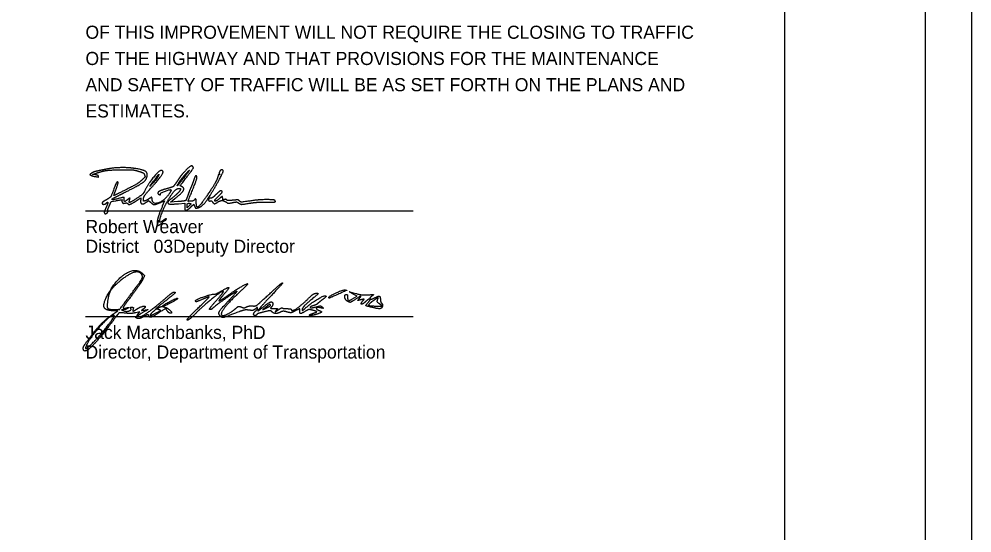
# Model space of a CAD drawing. Extents: x 0 to 34, y 0 to 22.
# Drawn here: x 23.82 to 34, y 5.49 to 10.97 of the extents above; entities that cross this region are included whole.
import ezdxf

# ---------------------------------------------------------------- set-up
doc = ezdxf.new("R2010")
doc.units = 0
for name, color, linetype in [('SH_Border', 7, 'Continuous'), ('SH_Cut_Line', 7, 'Continuous'), ('SH_Data', 7, 'Continuous'), ('SH_Text', 7, 'Continuous')]:
    doc.layers.add(name, color=color, linetype=linetype)

msp = doc.modelspace()

# ---------------------------------------------------------------- linework, layer by layer
at = {"layer": 'SH_Border'}
msp.add_line((32, 0.5), (32, 21.5), dxfattribs=at)
msp.add_lwpolyline([(1.5, 21.5), (33.5, 21.5), (33.5, 0.5), (1.5, 0.5)], close=True, dxfattribs=at)
at = {"layer": 'SH_Cut_Line'}
msp.add_lwpolyline([(0, 0), (34, 0), (34, 22), (0, 22)], close=True, dxfattribs=at)
at = {"layer": 'SH_Data'}
for p, q in [((24.528, 8.926), (28.028, 8.926)), ((24.528, 7.797), (28.028, 7.797))]:
    msp.add_line(p, q, dxfattribs=at)
at = {"layer": 'SH_Text'}
for p, q in [((24.99, 8.002), (24.99, 8.002)), ((27.129, 8.001), (27.129, 8.001)), ((25.311, 7.87), (25.311, 7.87)), ((25.356, 7.912), (25.356, 7.912)), ((25.727, 7.883), (25.727, 7.883)), ((26.504, 7.914), (26.504, 7.914)), ((27.582, 7.895), (27.582, 7.895))]:
    msp.add_line(p, q, dxfattribs=at)
for points in [[(24.633, 9.309), (24.603, 9.313), (24.63, 9.322)], [(25.249, 9.219), (25.216, 9.183), (25.256, 9.242)], [(24.782, 8.975), (24.803, 9.023), (24.852, 9.032)], [(25.182, 9.02), (25.202, 9.036), (25.223, 9.016)], [(25.331, 9.014), (25.374, 9.032), (25.349, 8.973)], [(25.514, 9.023), (25.435, 9.018), (25.484, 9.056)], [(25.521, 9), (25.59, 9.005), (25.59, 8.966)], [(25.636, 8.978), (25.613, 8.955), (25.613, 8.976)], [(25.662, 8.973), (25.684, 8.996), (25.694, 8.973)], [(27.393, 7.991), (27.43, 8.013), (27.389, 8.036)], [(24.843, 7.835), (24.873, 7.856), (24.835, 7.857)], [(25.085, 7.815), (25.107, 7.847), (25.065, 7.837)], [(26.453, 7.894), (26.423, 7.869), (26.464, 7.888)], [(27.642, 7.908), (27.698, 7.908), (27.669, 7.93)]]:
    msp.add_lwpolyline(points, dxfattribs=at)
for points in [[(25.045, 9.378), (24.973, 9.388), (24.809, 9.382), (24.736, 9.366)], [(25.183, 9.279), (25.197, 9.326), (25.145, 9.364), (25.045, 9.378)], [(25.665, 9.404), (25.656, 9.41), (25.569, 9.328), (25.541, 9.289)], [(25.591, 9.259), (25.672, 9.364), (25.686, 9.391), (25.665, 9.404)], [(24.59, 9.324), (24.574, 9.311), (24.574, 9.311), (24.588, 9.303)], [(24.588, 9.303), (24.596, 9.299), (24.618, 9.293), (24.636, 9.29)], [(24.647, 9.347), (24.625, 9.342), (24.6, 9.332), (24.59, 9.324)], [(24.63, 9.322), (24.708, 9.349), (24.802, 9.362), (24.927, 9.362)], [(24.666, 9.295), (24.664, 9.3), (24.649, 9.307), (24.633, 9.309)], [(24.636, 9.29), (24.663, 9.285), (24.669, 9.286), (24.666, 9.295)], [(24.736, 9.366), (24.709, 9.36), (24.669, 9.352), (24.647, 9.347)], [(24.927, 9.362), (25.036, 9.361), (25.059, 9.359), (25.102, 9.345)], [(24.965, 9.13), (25.097, 9.196), (25.173, 9.248), (25.183, 9.279)], [(25.102, 9.345), (25.142, 9.331), (25.153, 9.324), (25.159, 9.307)], [(25.159, 9.307), (25.165, 9.289), (25.163, 9.283), (25.143, 9.265)], [(25.336, 9.354), (25.312, 9.354), (25.202, 9.217), (25.161, 9.137)], [(25.228, 9.167), (25.322, 9.27), (25.371, 9.355), (25.336, 9.354)], [(25.295, 9.278), (25.287, 9.265), (25.267, 9.238), (25.249, 9.219)], [(25.256, 9.242), (25.295, 9.299), (25.322, 9.324), (25.295, 9.278)], [(25.541, 9.289), (25.532, 9.276), (25.512, 9.246), (25.495, 9.222)], [(25.572, 9.268), (25.526, 9.207), (25.499, 9.182), (25.526, 9.224)], [(25.526, 9.224), (25.544, 9.253), (25.584, 9.302), (25.615, 9.335)], [(25.615, 9.335), (25.644, 9.365), (25.628, 9.341), (25.572, 9.268)], [(25.675, 9.155), (25.712, 9.248), (25.723, 9.295), (25.708, 9.3)], [(25.708, 9.3), (25.704, 9.301), (25.694, 9.28), (25.685, 9.254)], [(25.944, 9.296), (25.936, 9.261), (25.895, 9.188), (25.836, 9.102)], [(25.928, 9.204), (25.988, 9.31), (26.006, 9.362), (25.983, 9.362)], [(25.957, 9.312), (25.952, 9.315), (25.946, 9.309), (25.944, 9.296)], [(25.983, 9.362), (25.971, 9.362), (25.953, 9.326), (25.96, 9.315)], [(25.96, 9.315), (25.963, 9.31), (25.962, 9.309), (25.957, 9.312)], [(24.836, 9.171), (24.803, 9.081), (24.793, 9.067), (24.748, 9.041)], [(24.866, 9.231), (24.861, 9.229), (24.847, 9.202), (24.836, 9.171)], [(24.849, 9.139), (24.873, 9.204), (24.879, 9.236), (24.866, 9.231)], [(25.143, 9.265), (25.105, 9.228), (25.056, 9.198), (24.944, 9.142)], [(25.148, 9.044), (25.148, 9.07), (25.169, 9.103), (25.228, 9.167)], [(25.434, 9.171), (25.371, 9.155), (25.306, 9.13), (25.302, 9.12)], [(25.413, 9.043), (25.446, 9.101), (25.506, 9.164), (25.526, 9.164)], [(25.495, 9.222), (25.471, 9.187), (25.46, 9.178), (25.434, 9.171)], [(25.484, 9.056), (25.559, 9.113), (25.589, 9.171), (25.552, 9.185)], [(25.526, 9.164), (25.536, 9.164), (25.544, 9.16), (25.544, 9.156)], [(25.552, 9.185), (25.539, 9.19), (25.543, 9.198), (25.591, 9.259)], [(25.655, 9.175), (25.648, 9.159), (25.633, 9.121), (25.623, 9.092)], [(25.685, 9.254), (25.676, 9.227), (25.662, 9.192), (25.655, 9.175)], [(25.725, 8.955), (25.768, 8.965), (25.848, 9.063), (25.928, 9.204)], [(24.813, 9.048), (24.813, 9.051), (24.827, 9.061), (24.845, 9.07)], [(24.833, 9.088), (24.831, 9.088), (24.838, 9.111), (24.849, 9.139)], [(24.944, 9.142), (24.885, 9.112), (24.835, 9.088), (24.833, 9.088)], [(24.845, 9.07), (24.863, 9.079), (24.917, 9.106), (24.965, 9.13)], [(24.942, 9.046), (24.942, 9.068), (24.935, 9.069), (24.87, 9.053)], [(25.161, 9.137), (25.147, 9.11), (25.123, 9.088), (25.062, 9.049)], [(25.241, 9.044), (25.238, 9.069), (25.231, 9.07), (25.203, 9.05)], [(25.424, 9.109), (25.371, 9.032), (25.247, 8.988), (25.241, 9.044)], [(25.302, 9.12), (25.3, 9.114), (25.303, 9.106), (25.309, 9.102)], [(25.309, 9.102), (25.324, 9.093), (25.331, 9.094), (25.331, 9.106)], [(25.331, 9.106), (25.331, 9.117), (25.433, 9.155), (25.442, 9.147)], [(25.442, 9.147), (25.444, 9.144), (25.436, 9.127), (25.424, 9.109)], [(25.544, 9.156), (25.544, 9.144), (25.494, 9.092), (25.449, 9.057)], [(25.623, 9.092), (25.612, 9.062), (25.601, 9.036), (25.598, 9.033)], [(25.653, 9.027), (25.622, 9.027), (25.621, 9.019), (25.675, 9.155)], [(25.836, 9.102), (25.754, 8.982), (25.712, 8.952), (25.712, 9.011)], [(25.921, 9.097), (25.895, 9.072), (25.874, 9.057), (25.868, 9.06)], [(25.91, 9.035), (25.91, 9.04), (25.927, 9.06), (25.949, 9.08)], [(25.972, 9.137), (25.967, 9.137), (25.944, 9.119), (25.921, 9.097)], [(25.949, 9.08), (25.984, 9.114), (25.994, 9.137), (25.972, 9.137)], [(25.994, 9.056), (25.994, 9.077), (25.983, 9.077), (25.959, 9.055)], [(24.748, 9.041), (24.725, 9.028), (24.706, 9.013), (24.706, 9.007)], [(24.706, 9.007), (24.706, 8.994), (24.737, 8.993), (24.75, 9.005)], [(24.749, 8.962), (24.738, 8.938), (24.729, 8.914), (24.729, 8.908)], [(24.75, 9.005), (24.768, 9.024), (24.768, 9.004), (24.749, 8.962)], [(24.768, 8.928), (24.764, 8.928), (24.77, 8.949), (24.782, 8.975)], [(24.87, 9.053), (24.817, 9.04), (24.813, 9.04), (24.813, 9.048)], [(24.852, 9.032), (24.908, 9.043), (24.924, 9.044), (24.917, 9.037)], [(24.917, 9.037), (24.914, 9.035), (24.916, 9.026), (24.92, 9.017)], [(24.92, 9.017), (24.926, 9.006), (24.933, 9.003), (24.95, 9.007)], [(24.975, 9.042), (24.949, 9.022), (24.942, 9.023), (24.942, 9.046)], [(24.95, 9.007), (24.962, 9.009), (24.974, 9.008), (24.977, 9.004)], [(24.999, 9.038), (25.004, 9.061), (25, 9.062), (24.975, 9.042)], [(24.977, 9.004), (24.986, 8.989), (25.017, 8.997), (25.061, 9.025)], [(25.062, 9.049), (25.007, 9.014), (24.992, 9.011), (24.999, 9.038)], [(25.061, 9.025), (25.086, 9.041), (25.11, 9.057), (25.114, 9.059)], [(25.114, 9.059), (25.12, 9.063), (25.122, 9.058), (25.119, 9.046)], [(25.119, 9.046), (25.112, 9.006), (25.146, 8.992), (25.182, 9.02)], [(25.165, 9.031), (25.151, 9.027), (25.148, 9.029), (25.148, 9.044)], [(25.203, 9.05), (25.191, 9.042), (25.174, 9.033), (25.165, 9.031)], [(25.223, 9.016), (25.249, 8.991), (25.275, 8.991), (25.331, 9.014)], [(25.349, 8.973), (25.317, 8.897), (25.293, 8.818), (25.293, 8.79)], [(25.325, 8.802), (25.313, 8.813), (25.371, 8.973), (25.413, 9.043)], [(25.449, 9.057), (25.426, 9.039), (25.407, 9.02), (25.407, 9.015)], [(25.407, 9.015), (25.407, 9), (25.447, 8.994), (25.521, 9)], [(25.598, 9.033), (25.596, 9.031), (25.558, 9.026), (25.514, 9.023)], [(25.59, 8.966), (25.59, 8.945), (25.592, 8.928), (25.594, 8.928)], [(25.594, 8.928), (25.605, 8.928), (25.642, 8.952), (25.662, 8.973)], [(25.613, 8.976), (25.613, 8.997), (25.625, 9.007), (25.647, 9.003)], [(25.647, 9.003), (25.657, 9.001), (25.655, 8.995), (25.636, 8.978)], [(25.689, 9.038), (25.684, 9.032), (25.667, 9.027), (25.653, 9.027)], [(25.712, 9.011), (25.712, 9.045), (25.703, 9.055), (25.689, 9.038)], [(25.694, 8.973), (25.702, 8.953), (25.706, 8.951), (25.725, 8.955)], [(25.868, 9.06), (25.854, 9.065), (25.837, 9.038), (25.849, 9.031)], [(25.849, 9.031), (25.853, 9.028), (25.86, 9.028), (25.865, 9.031)], [(25.865, 9.031), (25.869, 9.034), (25.878, 9.029), (25.884, 9.02)], [(25.884, 9.02), (25.898, 9), (25.915, 9), (25.943, 9.019)], [(25.959, 9.055), (25.935, 9.034), (25.91, 9.024), (25.91, 9.035)], [(25.943, 9.019), (25.968, 9.035), (26.008, 9.033), (26.037, 9.014)], [(26.012, 9.045), (25.997, 9.041), (25.994, 9.043), (25.994, 9.056)], [(26.036, 9.041), (26.033, 9.046), (26.023, 9.048), (26.012, 9.045)], [(26.102, 9.037), (26.06, 9.034), (26.04, 9.035), (26.036, 9.041)], [(26.037, 9.014), (26.05, 9.005), (26.061, 9.004), (26.099, 9.012)], [(26.099, 9.012), (26.138, 9.02), (26.147, 9.019), (26.162, 9.009)], [(26.174, 9.03), (26.164, 9.04), (26.152, 9.042), (26.102, 9.037)], [(26.162, 9.009), (26.184, 8.994), (26.207, 8.993), (26.291, 9.007)], [(26.317, 9.034), (26.195, 9.017), (26.188, 9.017), (26.174, 9.03)], [(26.291, 9.007), (26.326, 9.013), (26.397, 9.018), (26.448, 9.018)], [(26.553, 9.035), (26.547, 9.044), (26.386, 9.044), (26.317, 9.034)], [(26.448, 9.018), (26.54, 9.017), (26.562, 9.021), (26.553, 9.035)], [(24.729, 8.908), (24.729, 8.892), (24.758, 8.895), (24.767, 8.912)], [(24.767, 8.912), (24.772, 8.922), (24.772, 8.928), (24.768, 8.928)], [(25.293, 8.79), (25.293, 8.778), (25.295, 8.768), (25.298, 8.768)], [(25.298, 8.768), (25.308, 8.768), (25.354, 8.798), (25.354, 8.804)], [(25.36, 8.822), (25.342, 8.809), (25.326, 8.8), (25.325, 8.802)], [(25.354, 8.804), (25.354, 8.808), (25.362, 8.815), (25.373, 8.82)], [(25.392, 8.837), (25.392, 8.841), (25.377, 8.835), (25.36, 8.822)], [(25.373, 8.82), (25.383, 8.824), (25.392, 8.832), (25.392, 8.837)], [(24.779, 8.053), (24.865, 8.203), (25.073, 8.319), (25.139, 8.253)], [(25.13, 8.244), (25.104, 8.286), (24.978, 8.245), (24.883, 8.163)], [(25.139, 8.253), (25.158, 8.235), (25.158, 8.23), (25.139, 8.191)], [(24.883, 8.163), (24.816, 8.106), (24.777, 8.042), (24.766, 7.971)], [(24.99, 8.002), (25.112, 8.165), (25.144, 8.222), (25.13, 8.244)], [(25.139, 8.191), (25.128, 8.168), (25.077, 8.093), (25.024, 8.023)], [(26.487, 8.031), (26.562, 8.101), (26.628, 8.157), (26.634, 8.157)], [(26.634, 8.157), (26.639, 8.157), (26.587, 8.097), (26.518, 8.024)], [(24.835, 7.857), (24.737, 7.858), (24.714, 7.94), (24.779, 8.053)], [(25.369, 7.979), (25.419, 8.022), (25.465, 8.057), (25.47, 8.057)], [(25.47, 8.057), (25.495, 8.058), (25.472, 8.032), (25.386, 7.965)], [(26.002, 8.064), (25.992, 8.074), (25.782, 7.907), (25.704, 7.828)], [(26.142, 8.064), (26.093, 8.036), (25.905, 7.904), (25.891, 7.888)], [(25.908, 8.035), (25.914, 8.034), (25.943, 8.047), (25.974, 8.065)], [(25.924, 7.964), (25.97, 8.016), (26.005, 8.061), (26.002, 8.064)], [(25.974, 8.065), (26.052, 8.111), (26.065, 8.098), (26.005, 8.03)], [(26.168, 8.05), (26.069, 7.957), (25.979, 7.848), (25.979, 7.821)], [(26.033, 8.011), (26.113, 8.068), (26.244, 8.145), (26.26, 8.145)], [(26.077, 7.985), (26.123, 8.034), (26.152, 8.07), (26.142, 8.064)], [(26.26, 8.145), (26.265, 8.145), (26.224, 8.102), (26.168, 8.05)], [(26.895, 7.975), (26.94, 8.019), (26.977, 8.045), (26.995, 8.044)], [(26.995, 8.044), (27.019, 8.044), (27.016, 8.038), (26.967, 7.998)], [(27.129, 8.001), (27.129, 8.013), (27.282, 8.084), (27.301, 8.08)], [(27.301, 8.08), (27.322, 8.076), (27.323, 8.076), (27.201, 8.022)], [(27.389, 8.036), (27.346, 8.06), (27.345, 8.06), (27.448, 8.034)], [(24.766, 7.971), (24.755, 7.898), (24.776, 7.87), (24.844, 7.87)], [(24.844, 7.87), (24.891, 7.87), (24.895, 7.874), (24.99, 8.002)], [(25.024, 8.023), (24.972, 7.954), (24.929, 7.893), (24.929, 7.888)], [(25.108, 7.795), (25.131, 7.795), (25.257, 7.884), (25.369, 7.979)], [(25.386, 7.965), (25.293, 7.892), (25.271, 7.87), (25.315, 7.894)], [(25.356, 7.912), (25.376, 7.93), (25.508, 7.996), (25.513, 7.99)], [(25.513, 7.99), (25.519, 7.984), (25.377, 7.907), (25.359, 7.907)], [(25.705, 7.967), (25.705, 7.977), (25.892, 8.041), (25.908, 8.035)], [(25.786, 7.982), (25.723, 7.956), (25.704, 7.952), (25.705, 7.967)], [(25.727, 7.883), (25.798, 7.951), (25.854, 8.007), (25.85, 8.007)], [(25.85, 8.007), (25.847, 8.007), (25.818, 7.996), (25.786, 7.982)], [(25.858, 7.87), (25.848, 7.87), (25.877, 7.911), (25.924, 7.964)], [(26.005, 8.03), (25.977, 7.998), (25.954, 7.969), (25.954, 7.964)], [(25.954, 7.964), (25.954, 7.96), (25.99, 7.981), (26.033, 8.011)], [(25.97, 7.799), (25.945, 7.825), (25.973, 7.875), (26.077, 7.985)], [(26.312, 7.909), (26.345, 7.906), (26.369, 7.923), (26.487, 8.031)], [(26.518, 8.024), (26.388, 7.886), (26.356, 7.839), (26.439, 7.907)], [(26.439, 7.907), (26.487, 7.946), (26.529, 7.957), (26.529, 7.929)], [(26.729, 7.868), (26.729, 7.846), (26.825, 7.907), (26.895, 7.975)], [(26.967, 7.998), (26.893, 7.937), (26.842, 7.883), (26.842, 7.866)], [(26.876, 7.884), (26.93, 7.933), (27.077, 8.023), (27.094, 8.017)], [(27.06, 7.976), (27.033, 7.955), (27.008, 7.935), (27.004, 7.931)], [(27.094, 8.017), (27.102, 8.014), (27.087, 7.996), (27.06, 7.976)], [(27.201, 8.022), (27.138, 7.994), (27.129, 7.991), (27.129, 8.001)], [(27.33, 7.957), (27.304, 7.971), (27.293, 8.032), (27.317, 8.032)], [(27.317, 8.032), (27.324, 8.032), (27.329, 8.018), (27.329, 8.001)], [(27.329, 8.001), (27.329, 7.964), (27.344, 7.962), (27.393, 7.991)], [(27.405, 7.975), (27.365, 7.949), (27.352, 7.945), (27.33, 7.957)], [(27.453, 7.987), (27.477, 8.016), (27.461, 8.012), (27.405, 7.975)], [(27.472, 7.975), (27.439, 7.967), (27.437, 7.968), (27.453, 7.987)], [(27.448, 8.034), (27.469, 8.028), (27.514, 8.026), (27.548, 8.028)], [(27.492, 7.964), (27.507, 7.982), (27.505, 7.983), (27.472, 7.975)], [(27.521, 7.955), (27.489, 7.925), (27.466, 7.932), (27.492, 7.964)], [(27.546, 7.943), (27.577, 7.976), (27.555, 7.987), (27.521, 7.955)], [(27.582, 7.895), (27.527, 7.908), (27.522, 7.915), (27.546, 7.943)], [(27.548, 8.028), (27.603, 8.031), (27.608, 8.029), (27.588, 8.014)], [(27.589, 7.953), (27.546, 7.922), (27.563, 7.908), (27.642, 7.908)], [(27.588, 8.014), (27.559, 7.993), (27.582, 7.976), (27.616, 7.994)], [(27.65, 7.976), (27.66, 8.001), (27.651, 7.998), (27.589, 7.953)], [(27.616, 7.994), (27.656, 8.016), (27.679, 8.01), (27.679, 7.979)], [(27.669, 7.93), (27.649, 7.946), (27.643, 7.959), (27.65, 7.976)], [(27.679, 7.979), (27.679, 7.963), (27.686, 7.944), (27.694, 7.936)], [(24.936, 7.869), (24.913, 7.868), (24.914, 7.867), (24.94, 7.857)], [(24.929, 7.888), (24.929, 7.884), (24.945, 7.883), (24.964, 7.888)], [(24.979, 7.883), (24.969, 7.876), (24.949, 7.87), (24.936, 7.869)], [(24.94, 7.857), (24.97, 7.845), (25.026, 7.869), (25.009, 7.887)], [(24.964, 7.888), (24.989, 7.894), (24.993, 7.892), (24.979, 7.883)], [(25.009, 7.887), (25.004, 7.891), (25.01, 7.895), (25.022, 7.895)], [(25.022, 7.895), (25.037, 7.895), (25.042, 7.889), (25.037, 7.876)], [(25.037, 7.876), (25.029, 7.853), (25.041, 7.852), (25.074, 7.874)], [(25.074, 7.874), (25.102, 7.894), (25.167, 7.912), (25.167, 7.9)], [(25.152, 7.846), (25.101, 7.817), (25.081, 7.795), (25.108, 7.795)], [(25.145, 7.876), (25.126, 7.862), (25.128, 7.861), (25.161, 7.865)], [(25.167, 7.9), (25.167, 7.895), (25.157, 7.884), (25.145, 7.876)], [(25.161, 7.865), (25.198, 7.871), (25.198, 7.871), (25.152, 7.846)], [(25.258, 7.854), (25.213, 7.813), (25.225, 7.804), (25.283, 7.834)], [(25.311, 7.87), (25.293, 7.877), (25.277, 7.872), (25.258, 7.854)], [(25.283, 7.834), (25.329, 7.858), (25.333, 7.862), (25.311, 7.87)], [(25.315, 7.894), (25.328, 7.901), (25.351, 7.903), (25.368, 7.899)], [(25.401, 7.857), (25.384, 7.881), (25.382, 7.881), (25.316, 7.838)], [(25.359, 7.907), (25.354, 7.907), (25.353, 7.909), (25.356, 7.912)], [(25.368, 7.899), (25.404, 7.889), (25.463, 7.832), (25.436, 7.832)], [(25.436, 7.832), (25.426, 7.832), (25.411, 7.844), (25.401, 7.857)], [(25.617, 7.758), (25.607, 7.758), (25.656, 7.815), (25.727, 7.883)], [(25.891, 7.888), (25.883, 7.878), (25.868, 7.87), (25.858, 7.87)], [(26.169, 7.847), (26.023, 7.789), (25.988, 7.781), (25.97, 7.799)], [(25.998, 7.807), (26.019, 7.807), (26.101, 7.853), (26.137, 7.885)], [(26.137, 7.885), (26.157, 7.903), (26.17, 7.906), (26.194, 7.897)], [(26.275, 7.864), (26.246, 7.868), (26.206, 7.861), (26.169, 7.847)], [(26.194, 7.897), (26.214, 7.889), (26.233, 7.89), (26.249, 7.899)], [(26.249, 7.899), (26.262, 7.906), (26.291, 7.911), (26.312, 7.909)], [(26.344, 7.878), (26.329, 7.864), (26.307, 7.86), (26.275, 7.864)], [(26.341, 7.807), (26.323, 7.807), (26.327, 7.84), (26.348, 7.857)], [(26.367, 7.886), (26.367, 7.893), (26.357, 7.89), (26.344, 7.878)], [(26.348, 7.857), (26.359, 7.866), (26.367, 7.879), (26.367, 7.886)], [(26.436, 7.845), (26.397, 7.836), (26.363, 7.824), (26.359, 7.818)], [(26.52, 7.847), (26.509, 7.858), (26.489, 7.858), (26.436, 7.845)], [(26.504, 7.914), (26.504, 7.927), (26.48, 7.918), (26.453, 7.894)], [(26.464, 7.888), (26.486, 7.899), (26.504, 7.911), (26.504, 7.914)], [(26.514, 7.897), (26.503, 7.886), (26.509, 7.882), (26.541, 7.882)], [(26.529, 7.929), (26.529, 7.92), (26.523, 7.906), (26.514, 7.897)], [(26.616, 7.845), (26.585, 7.828), (26.538, 7.829), (26.52, 7.847)], [(26.541, 7.882), (26.579, 7.882), (26.581, 7.88), (26.565, 7.861)], [(26.565, 7.861), (26.553, 7.846), (26.56, 7.848), (26.587, 7.867)], [(26.587, 7.867), (26.609, 7.882), (26.629, 7.891), (26.633, 7.887)], [(26.681, 7.845), (26.654, 7.852), (26.631, 7.852), (26.616, 7.845)], [(26.633, 7.887), (26.637, 7.883), (26.66, 7.88), (26.685, 7.88)], [(26.77, 7.856), (26.732, 7.837), (26.714, 7.835), (26.681, 7.845)], [(26.685, 7.88), (26.709, 7.88), (26.729, 7.875), (26.729, 7.868)], [(26.817, 7.856), (26.817, 7.879), (26.816, 7.879), (26.77, 7.856)], [(26.879, 7.853), (26.834, 7.826), (26.817, 7.827), (26.817, 7.856)], [(26.842, 7.866), (26.842, 7.859), (26.857, 7.867), (26.876, 7.884)], [(26.962, 7.861), (26.923, 7.871), (26.906, 7.869), (26.879, 7.853)], [(26.97, 7.915), (26.921, 7.899), (26.94, 7.885), (26.992, 7.899)], [(26.948, 7.826), (26.962, 7.831), (26.982, 7.838), (26.992, 7.842)], [(26.992, 7.842), (27.003, 7.846), (26.992, 7.853), (26.962, 7.861)], [(27.004, 7.931), (27.001, 7.927), (26.986, 7.919), (26.97, 7.915)], [(26.992, 7.899), (27.03, 7.909), (27.045, 7.909), (27.058, 7.897)], [(27.039, 7.889), (27.002, 7.898), (26.989, 7.875), (27.023, 7.862)], [(27.023, 7.862), (27.054, 7.85), (27.045, 7.835), (26.998, 7.82)], [(27.058, 7.897), (27.07, 7.884), (27.067, 7.882), (27.039, 7.889)], [(27.7, 7.902), (27.692, 7.881), (27.651, 7.878), (27.582, 7.895)], [(27.694, 7.936), (27.701, 7.928), (27.704, 7.913), (27.7, 7.902)], [(24.835, 7.806), (24.814, 7.827), (24.596, 7.601), (24.55, 7.511)], [(24.592, 7.593), (24.669, 7.693), (24.749, 7.77), (24.843, 7.835)], [(24.62, 7.529), (24.687, 7.598), (24.843, 7.798), (24.835, 7.806)], [(24.924, 7.835), (24.89, 7.838), (24.879, 7.828), (24.802, 7.726)], [(25.065, 7.837), (25.025, 7.828), (25.002, 7.827), (24.924, 7.835)], [(25.084, 7.775), (25.066, 7.782), (25.066, 7.786), (25.085, 7.815)], [(25.151, 7.795), (25.125, 7.78), (25.095, 7.771), (25.084, 7.775)], [(25.202, 7.809), (25.199, 7.817), (25.18, 7.812), (25.151, 7.795)], [(25.316, 7.838), (25.248, 7.794), (25.21, 7.784), (25.202, 7.809)], [(25.704, 7.828), (25.667, 7.789), (25.627, 7.758), (25.617, 7.758)], [(25.979, 7.821), (25.979, 7.814), (25.988, 7.807), (25.998, 7.807)], [(26.359, 7.818), (26.356, 7.812), (26.348, 7.807), (26.341, 7.807)], [(26.998, 7.82), (26.952, 7.805), (26.904, 7.81), (26.948, 7.826)], [(24.802, 7.726), (24.65, 7.524), (24.504, 7.395), (24.504, 7.462)], [(24.504, 7.462), (24.504, 7.472), (24.544, 7.531), (24.592, 7.593)], [(24.55, 7.511), (24.518, 7.45), (24.55, 7.458), (24.62, 7.529)]]:
    msp.add_open_spline(points, degree=2, dxfattribs=at)

# ---------------------------------------------------------------- texts
for s, p in [('OF THIS IMPROVEMENT WILL NOT REQUIRE THE CLOSING TO TRAFFIC', (24.528, 10.761)), ('OF THE HIGHWAY AND THAT PROVISIONS FOR THE MAINTENANCE', (24.528, 10.481)), ('AND SAFETY OF TRAFFIC WILL BE AS SET FORTH ON THE PLANS AND', (24.528, 10.201)), ('ESTIMATES.', (24.528, 9.921)), ('Robert Weaver', (24.528, 8.686)), ('District       Deputy Director', (24.528, 8.476)), ('              03', (24.528, 8.476)), ('Jack Marchbanks, PhD', (24.528, 7.557)), ('Director, Department of Transportation', (24.528, 7.347))]:
    msp.add_text(s, height=0.14, dxfattribs=at).set_placement(p)

doc.saveas('drawing.dxf')
